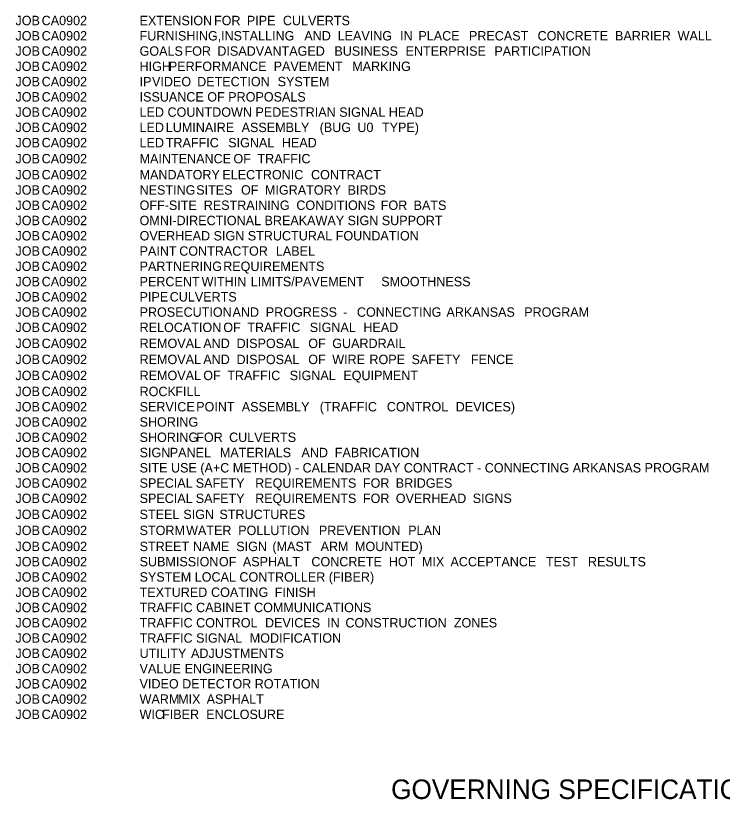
# Model space of a CAD drawing. Extents: x 1226673 to 1228148, y 151313 to 152324.
# Drawn here: x 1227451 to 1227903, y 151313 to 151813 of the extents above; entities that cross this region are included whole.
import ezdxf

# ---------------------------------------------------------------- set-up
doc = ezdxf.new("R2010")
doc.units = 0
doc.layers.add('R_Border Notes', color=7, linetype='Continuous')
doc.layers.add('R_Dimension', color=7, linetype='Continuous')

msp = doc.modelspace()

# ---------------------------------------------------------------- texts
at = {"layer": 'R_Border Notes'}
msp.add_text('GOVERNING SPECIFICATIONS & GENERAL NOTES ', height=12.5, dxfattribs=at).set_placement((1227691.22, 151312.82))
at = {"layer": 'R_Dimension'}
for s, p in [('JOB', (1227451.32, 151807.06)), (' CA0902', (1227465.82, 151807.06)), ('EXTENSION', (1227530.58, 151807.06)), (' FOR', (1227575.88, 151807.06)), (' PIPE', (1227596.86, 151807.06)), (' CULVERTS', (1227619.87, 151807.06)), ('JOB', (1227451.32, 151797.31)), (' CA0902', (1227465.82, 151797.31)), ('FURNISHING,', (1227530.58, 151797.31)), (' INSTALLING', (1227580.37, 151797.31)), (' AND', (1227633.57, 151797.31)), (' LEAVING', (1227654.83, 151797.31)), (' IN', (1227694.7, 151797.31)), (' PLACE', (1227706.42, 151797.31)), (' PRECAST', (1227738.69, 151797.31)), (' CONCRETE', (1227782.53, 151797.31)), (' BARRIER', (1227831.99, 151797.31)), (' WALL', (1227871.96, 151797.31)), ('JOB', (1227451.32, 151787.56)), (' CA0902', (1227465.82, 151787.56)), ('GOALS', (1227530.58, 151787.56)), (' FOR', (1227557.03, 151787.56)), (' DISADVANTAGED', (1227578.01, 151787.56)), (' BUSINESS', (1227652.75, 151787.56)), (' ENTERPRISE', (1227698.25, 151787.56)), (' PARTICIPATION', (1227754.89, 151787.56)), ('JOB', (1227451.32, 151777.81)), (' CA0902', (1227465.82, 151777.81)), ('HIGH', (1227530.58, 151777.81)), (' PERFORMANCE', (1227547.02, 151777.81)), (' PAVEMENT', (1227613.96, 151777.81)), (' MARKING', (1227664.14, 151777.81)), ('JOB', (1227451.32, 151768.06)), (' CA0902', (1227465.82, 151768.06)), ('IP', (1227530.58, 151768.06)), (' VIDEO', (1227536.29, 151768.06)), (' DETECTION', (1227565.11, 151768.06)), (' SYSTEM', (1227616.51, 151768.06)), ('JOB', (1227451.32, 151758.31)), (' CA0902', (1227465.82, 151758.31)), ('ISSUANCE OF PROPOSALS', (1227530.58, 151758.31)), ('JOB', (1227451.32, 151748.56)), (' CA0902', (1227465.82, 151748.56)), ('LED COUNTDOWN PEDESTRIAN SIGNAL HEAD', (1227530.58, 151748.56)), (' (BUG', (1227643.35, 151738.81)), (' TYPE)', (1227683.13, 151738.81)), ('JOB', (1227451.32, 151738.81)), (' CA0902', (1227465.82, 151738.81)), ('LED', (1227530.58, 151738.81)), (' LUMINAIRE', (1227545.08, 151738.81)), (' ASSEMBLY', (1227593.51, 151738.81)), (' U0', (1227667.44, 151738.81)), ('JOB', (1227451.32, 151729.06)), (' CA0902', (1227465.82, 151729.06)), ('LED', (1227530.58, 151729.06)), (' TRAFFIC', (1227545.08, 151729.06)), (' SIGNAL', (1227584.95, 151729.06)), (' HEAD', (1227619.21, 151729.06)), ('JOB', (1227451.32, 151718.82)), (' CA0902', (1227465.82, 151718.82)), ('MAINTENANCE', (1227530.58, 151718.82)), (' OF', (1227588.31, 151718.82)), (' TRAFFIC', (1227603.62, 151718.82)), ('JOB', (1227451.32, 151708.59)), (' CA0902', (1227465.82, 151708.59)), ('MANDATORY', (1227530.58, 151708.59)), (' ELECTRONIC', (1227581.22, 151708.59)), (' CONTRACT', (1227637.82, 151708.59)), ('JOB', (1227451.32, 151698.84)), (' CA0902', (1227465.82, 151698.84)), ('NESTING', (1227530.58, 151698.84)), (' SITES', (1227564.54, 151698.84)), (' OF', (1227593.13, 151698.84)), (' MIGRATORY', (1227608.43, 151698.84)), (' BIRDS', (1227661.21, 151698.84)), ('JOB', (1227451.32, 151689.09)), (' CA0902', (1227465.82, 151689.09)), ('OFF-SITE', (1227530.58, 151689.09)), (' RESTRAINING', (1227569.32, 151689.09)), (' CONDITIONS', (1227628.47, 151689.09)), (' FOR', (1227682.37, 151689.09)), (' BATS', (1227703.35, 151689.09)), ('JOB', (1227451.32, 151679.34)), (' CA0902', (1227465.82, 151679.34)), ('OMNI-DIRECTIONAL BREAKAWAY SIGN SUPPORT', (1227530.58, 151679.34)), ('JOB', (1227451.32, 151669.59)), (' CA0902', (1227465.82, 151669.59)), ('OVERHEAD SIGN STRUCTURAL FOUNDATION', (1227530.58, 151669.59)), ('JOB', (1227451.32, 151659.84)), (' CA0902', (1227465.82, 151659.84)), ('PAINT', (1227530.58, 151659.84)), (' CONTRACTOR', (1227553.68, 151659.84)), (' LABEL', (1227615.38, 151659.84)), ('JOB', (1227451.32, 151650.09)), (' CA0902', (1227465.82, 151650.09)), ('PARTNERING', (1227530.58, 151650.09)), (' REQUIREMENTS', (1227581.74, 151650.09)), ('JOB', (1227451.32, 151640.34)), (' CA0902', (1227465.82, 151640.34)), ('PERCENT', (1227530.58, 151640.34)), (' WITHIN', (1227567.95, 151640.34)), (' LIMITS/PAVEMENT', (1227599.32, 151640.34)), (' SMOOTHNESS', (1227682.66, 151640.34)), ('JOB', (1227451.32, 151630.59)), (' CA0902', (1227465.82, 151630.59)), ('PIPE', (1227530.58, 151630.59)), (' CULVERTS', (1227547.58, 151630.59)), ('JOB', (1227451.32, 151620.84)), (' CA0902', (1227465.82, 151620.84)), ('PROSECUTION', (1227530.58, 151620.84)), (' AND', (1227587.69, 151620.84)), (' PROGRESS', (1227608.95, 151620.84)), (' CONNECTING', (1227667.16, 151620.84)), (' ARKANSAS', (1227724.32, 151620.84)), (' PROGRAM', (1227773.98, 151620.84)), (' -', (1227658.23, 151620.84)), ('JOB', (1227451.32, 151611.09)), (' CA0902', (1227465.82, 151611.09)), ('RELOCATION', (1227530.58, 151611.09)), (' OF', (1227581.84, 151611.09)), (' TRAFFIC', (1227597.14, 151611.09)), (' SIGNAL', (1227637.02, 151611.09)), (' HEAD', (1227671.27, 151611.09)), ('JOB', (1227451.32, 151600.85)), (' CA0902', (1227465.82, 151600.85)), ('REMOVAL', (1227530.58, 151600.85)), (' AND', (1227569.03, 151600.85)), (' DISPOSAL', (1227590.29, 151600.85)), (' OF', (1227636.07, 151600.85)), (' GUARDRAIL', (1227651.38, 151600.85)), ('JOB', (1227451.32, 151590.61)), (' CA0902', (1227465.82, 151590.61)), ('REMOVAL', (1227530.58, 151590.61)), (' AND', (1227569.03, 151590.61)), (' DISPOSAL', (1227590.29, 151590.61)), (' OF', (1227636.07, 151590.61)), (' WIRE', (1227651.38, 151590.61)), (' ROPE', (1227675.14, 151590.61)), (' SAFETY', (1227702.03, 151590.61)), (' FENCE', (1227739.96, 151590.61)), ('JOB', (1227451.32, 151580.37)), (' CA0902', (1227465.82, 151580.37)), ('REMOVAL', (1227530.58, 151580.37)), (' OF', (1227569.03, 151580.37)), (' TRAFFIC', (1227584.34, 151580.37)), (' SIGNAL', (1227624.21, 151580.37)), (' EQUIPMENT', (1227658.47, 151580.37)), ('JOB', (1227451.32, 151570.14)), (' CA0902', (1227465.82, 151570.14)), ('ROCK', (1227530.58, 151570.14)), (' FILL', (1227551.17, 151570.14)), ('JOB', (1227451.32, 151560.39)), (' CA0902', (1227465.82, 151560.39)), ('SERVICE', (1227530.58, 151560.39)), (' POINT', (1227564.5, 151560.39)), (' ASSEMBLY', (1227593.6, 151560.39)), (' (TRAFFIC', (1227643.44, 151560.39)), (' CONTROL', (1227686.25, 151560.39)), (' DEVICES)', (1227730.23, 151560.39)), ('JOB', (1227451.32, 151550.64)), (' CA0902', (1227465.82, 151550.64)), ('SHORING', (1227530.58, 151550.64)), ('JOB', (1227451.32, 151540.89)), (' CA0902', (1227465.82, 151540.89)), ('SHORING', (1227530.58, 151540.89)), (' FOR', (1227564.54, 151540.89)), (' CULVERTS', (1227585.52, 151540.89)), ('JOB', (1227451.32, 151531.14)), (' CA0902', (1227465.82, 151531.14)), ('SIGN', (1227530.58, 151531.14)), (' PANEL', (1227547.63, 151531.14)), (' MATERIALS', (1227579.62, 151531.14)), (' AND', (1227631.73, 151531.14)), (' FABRICATION', (1227652.99, 151531.14)), ('JOB', (1227451.32, 151521.39)), (' CA0902', (1227465.82, 151521.39)), ('SITE USE (A+C METHOD) - CALENDAR DAY CONTRACT - CONNECTING ARKANSAS PROGRAM', (1227530.58, 151521.39)), ('JOB', (1227451.32, 151511.64)), (' CA0902', (1227465.82, 151511.64)), ('SPECIAL', (1227530.58, 151511.64)), (' SAFETY', (1227564.21, 151511.64)), (' REQUIREMENTS', (1227602.15, 151511.64)), (' FOR', (1227670.99, 151511.64)), (' BRIDGES', (1227691.96, 151511.64)), ('JOB', (1227451.32, 151501.89)), (' CA0902', (1227465.82, 151501.89)), ('SPECIAL', (1227530.58, 151501.89)), (' SAFETY', (1227564.21, 151501.89)), (' REQUIREMENTS', (1227602.15, 151501.89)), (' FOR', (1227670.99, 151501.89)), (' OVERHEAD', (1227691.96, 151501.89)), (' SIGNS', (1227741.1, 151501.89)), ('JOB', (1227451.32, 151491.65)), (' CA0902', (1227465.82, 151491.65)), ('STEEL', (1227530.58, 151491.65)), (' SIGN', (1227556.28, 151491.65)), (' STRUCTURES', (1227579.33, 151491.65)), ('JOB', (1227451.32, 151481.41)), (' CA0902', (1227465.82, 151481.41)), ('STORM', (1227530.58, 151481.41)), (' WATER', (1227558.07, 151481.41)), (' POLLUTION', (1227591.33, 151481.41)), (' PREVENTION', (1227642.83, 151481.41)), (' PLAN', (1227699.9, 151481.41)), ('JOB', (1227451.32, 151471.17)), (' CA0902', (1227465.82, 151471.17)), ('STREET', (1227530.58, 151471.17)), (' NAME', (1227562.47, 151471.17)), (' SIGN', (1227590.1, 151471.17)), (' (MAST', (1227613.16, 151471.17)), (' ARM', (1227643.96, 151471.17)), (' MOUNTED)', (1227665.93, 151471.17)), ('JOB', (1227451.32, 151461.42)), (' CA0902', (1227465.82, 151461.42)), ('SUBMISSION', (1227530.58, 151461.42)), (' OF', (1227579, 151461.42)), (' ASPHALT', (1227594.31, 151461.42)), (' CONCRETE', (1227638.06, 151461.42)), (' HOT', (1227687.52, 151461.42)), (' MIX', (1227708.69, 151461.42)), (' ACCEPTANCE', (1227726.88, 151461.42)), (' TEST', (1227787.87, 151461.42)), (' RESULTS', (1227814.7, 151461.42)), ('JOB', (1227451.32, 151451.67)), (' CA0902', (1227465.82, 151451.67)), ('SYSTEM LOCAL CONTROLLER (FIBER)', (1227530.58, 151451.68)), ('JOB', (1227451.32, 151441.92)), (' CA0902', (1227465.82, 151441.92)), ('TEXTURED', (1227530.58, 151441.92)), (' COATING', (1227573.99, 151441.92)), (' FINISH', (1227614.62, 151441.92)), ('JOB', (1227451.32, 151432.17)), (' CA0902', (1227465.82, 151432.17)), ('TRAFFIC CABINET COMMUNICATIONS', (1227530.58, 151432.18)), ('JOB', (1227451.32, 151422.42)), (' CA0902', (1227465.82, 151422.42)), ('TRAFFIC', (1227530.58, 151422.42)), (' CONTROL', (1227564.45, 151422.42)), (' DEVICES', (1227608.43, 151422.42)), (' IN', (1227648.07, 151422.42)), (' CONSTRUCTION', (1227659.79, 151422.42)), (' ZONES', (1227729.05, 151422.42)), ('JOB', (1227451.32, 151412.67)), (' CA0902', (1227465.82, 151412.67)), ('TRAFFIC', (1227530.58, 151412.67)), (' SIGNAL', (1227564.45, 151412.67)), (' MODIFICATION', (1227598.7, 151412.67)), ('JOB', (1227451.32, 151402.92)), (' CA0902', (1227465.82, 151402.92)), ('UTILITY', (1227530.58, 151402.92)), (' ADJUSTMENTS', (1227561.19, 151402.92)), ('JOB', (1227451.32, 151393.17)), (' CA0902', (1227465.82, 151393.17)), ('VALUE', (1227530.58, 151393.17)), (' ENGINEERING', (1227557.13, 151393.17)), ('JOB', (1227451.32, 151383.42)), (' CA0902', (1227465.82, 151383.42)), ('VIDEO DETECTOR ROTATION', (1227530.58, 151383.43)), ('JOB', (1227451.32, 151373.67)), (' CA0902', (1227465.82, 151373.67)), (' ASPHALT', (1227571.16, 151373.67)), ('WARM', (1227530.58, 151373.67)), (' MIX', (1227552.97, 151373.67)), ('JOB', (1227451.32, 151363.92)), (' CA0902', (1227465.82, 151363.92)), ('WIC', (1227530.58, 151363.92)), (' FIBER', (1227542.72, 151363.92)), (' ENCLOSURE', (1227570.88, 151363.92))]:
    msp.add_text(s, height=6, dxfattribs=at).set_placement(p)

doc.saveas('drawing.dxf')
